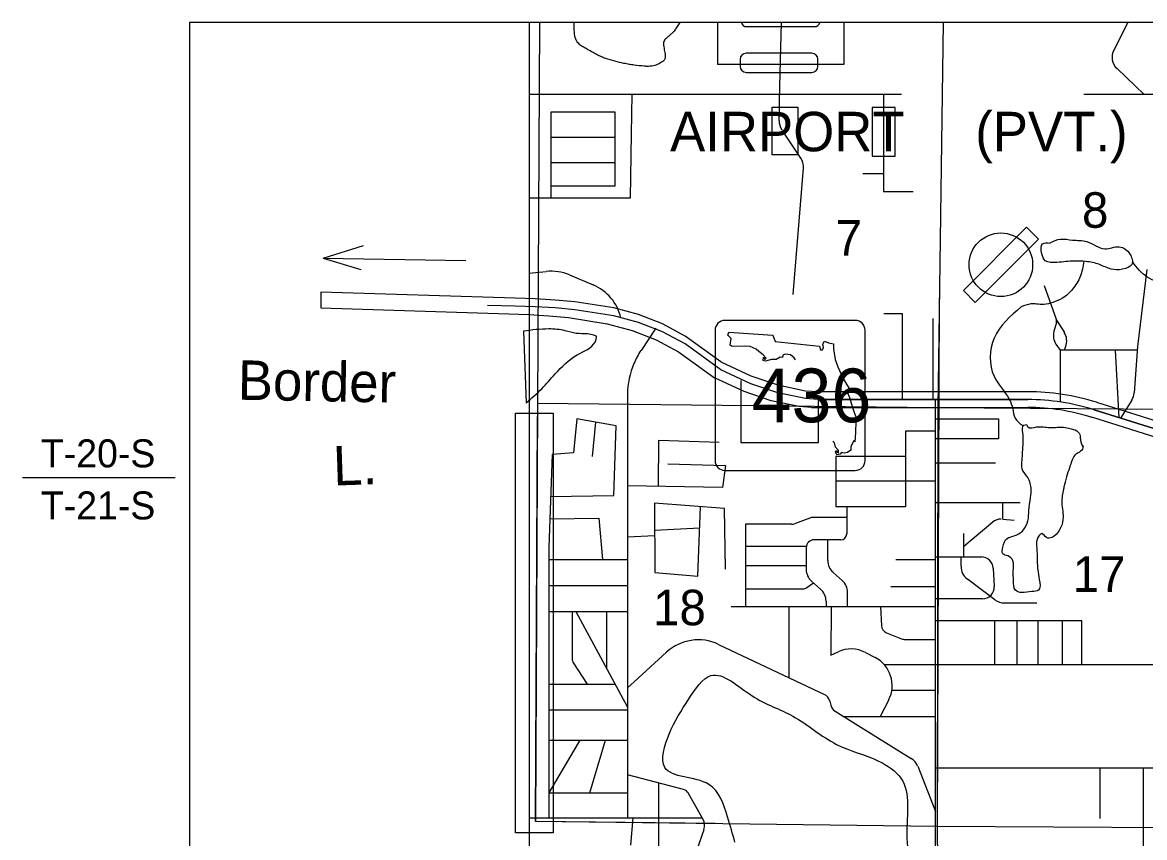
# Model space of a CAD drawing. Extents: x 2157516 to 2331756, y 2153820 to 2265756.
# Drawn here: x 2219640 to 2249249, y 2201230 to 2222724 of the extents above; entities that cross this region are included whole.
import ezdxf

# ---------------------------------------------------------------- set-up
doc = ezdxf.new("R2010")
doc.units = 0
for name, color, linetype in [('Default', 7, 'Continuous'), ('MapOutline_dp', 7, 'Continuous'), ('TextNotes', 7, 'Continuous')]:
    doc.layers.add(name, color=color, linetype=linetype)

msp = doc.modelspace()

# ---------------------------------------------------------------- linework, layer by layer
at = {"layer": 'Default'}
for p, q in [((2233280, 2222724), (2233232, 2212675)), ((2238754, 2222613), (2240534, 2222613)), ((2239629, 2221047), (2239669, 2222724)), ((2243932, 2222724), (2243791, 2212557)), ((2248805, 2222724), (2248437, 2221997)), ((2240472, 2221910), (2238734, 2221910)), ((2238578, 2221754), (2238578, 2221563)), ((2240628, 2221563), (2240628, 2221754)), ((2238734, 2221407), (2240472, 2221407)), ((2248522, 2221506), (2249008, 2221047)), ((2239608, 2220137), (2239629, 2221047)), ((2249008, 2221047), (2249234, 2220833)), ((2233004, 2220833), (2242838, 2220833)), ((2235711, 2219781), (2235728, 2220833)), ((2242359, 2220833), (2242359, 2218262)), ((2247650, 2220833), (2255920, 2220833)), ((2233594, 2218096), (2233594, 2220363)), ((2233594, 2220363), (2235271, 2220363)), ((2235271, 2220363), (2235271, 2218408)), ((2233594, 2219702), (2235271, 2219702)), ((2235682, 2218096), (2235711, 2219781)), ((2240178, 2219146), (2239754, 2219781)), ((2233594, 2219032), (2235271, 2219032)), ((2239977, 2215552), (2240246, 2218881)), ((2241814, 2218741), (2242359, 2218741)), ((2235271, 2218408), (2233599, 2218408)), ((2233022, 2218096), (2235682, 2218096)), ((2242359, 2218262), (2243142, 2218262)), ((2227571, 2216507), (2228636, 2216842)), ((2246760, 2216903), (2246761, 2216913)), ((2227571, 2216507), (2231343, 2216442)), ((2227571, 2216507), (2228565, 2216206)), ((2233005, 2216109), (2233457, 2216157)), ((2234076, 2216065), (2234701, 2215801)), ((2249311, 2216208), (2249064, 2214181)), ((2246601, 2215783), (2246919, 2214903)), ((2227515, 2215615), (2227515, 2215199)), ((2227515, 2215615), (2227515, 2215201)), ((2242367, 2215047), (2242854, 2215047)), ((2242854, 2215047), (2242854, 2212780)), ((2241613, 2214867), (2238177, 2214867)), ((2243669, 2212780), (2243669, 2214915)), ((2246923, 2214808), (2246859, 2214578)), ((2246926, 2214875), (2247132, 2214545)), ((2232862, 2214583), (2232929, 2212694)), ((2236354, 2214659), (2235962, 2214075)), ((2237917, 2214607), (2237917, 2211172)), ((2241873, 2211172), (2241873, 2214607)), ((2246911, 2214239), (2247021, 2214082)), ((2247167, 2214176), (2247131, 2214082)), ((2249064, 2214181), (2248974, 2212955)), ((2249057, 2214082), (2247021, 2214082)), ((2247021, 2214082), (2247021, 2212717)), ((2248473, 2214082), (2248566, 2212306)), ((2238598, 2213285), (2238598, 2211649)), ((2240632, 2212988), (2246167, 2212988)), ((2235608, 2212913), (2235608, 2201749)), ((2240632, 2212780), (2246167, 2212780)), ((2246167, 2212780), (2240632, 2212780)), ((2240647, 2211649), (2240647, 2212780)), ((2243735, 2196078), (2243735, 2212780)), ((2247984, 2212708), (2256111, 2210143)), ((2248910, 2212762), (2248611, 2212292)), ((2233232, 2212675), (2233179, 2201654)), ((2243791, 2212557), (2233232, 2212675)), ((2240462, 2212571), (2242532, 2212571)), ((2242532, 2212571), (2246167, 2212571)), ((2243791, 2212557), (2243775, 2201524)), ((2254920, 2212483), (2243791, 2212557)), ((2247922, 2212509), (2256048, 2209944)), ((2256048, 2209944), (2247922, 2212509)), ((2234272, 2212273), (2234183, 2211375)), ((2235303, 2212083), (2234272, 2212273)), ((2234763, 2212183), (2234675, 2211282)), ((2243735, 2212273), (2245391, 2212273)), ((2245391, 2212273), (2245391, 2211748)), ((2246131, 2212123), (2246131, 2212123)), ((2255985, 2209746), (2247859, 2212311)), ((2235242, 2210245), (2235303, 2212083)), ((2242953, 2209956), (2242953, 2211956)), ((2242953, 2211956), (2243735, 2211956)), ((2236419, 2210490), (2236435, 2211709)), ((2236435, 2211709), (2238022, 2211652)), ((2238598, 2211649), (2240647, 2211649)), ((2245391, 2211748), (2243735, 2211748)), ((2233615, 2211334), (2233528, 2208886)), ((2234183, 2211375), (2233615, 2211334)), ((2242933, 2211274), (2241102, 2211274)), ((2241102, 2211274), (2241102, 2209956)), ((2236668, 2211082), (2238188, 2211042)), ((2238188, 2211042), (2238112, 2210457)), ((2238177, 2210911), (2241613, 2210911)), ((2243735, 2211112), (2245312, 2211112)), ((2241102, 2210634), (2243735, 2210634)), ((2238112, 2210457), (2235608, 2210506)), ((2233575, 2210224), (2235242, 2210245)), ((2238169, 2209910), (2236319, 2210051)), ((2236319, 2210051), (2236325, 2208215)), ((2243735, 2210068), (2245969, 2210068)), ((2245511, 2209621), (2245511, 2210068)), ((2237460, 2208125), (2237535, 2209958)), ((2238188, 2208310), (2238169, 2209910)), ((2241102, 2209956), (2242953, 2209956)), ((2241389, 2209956), (2241389, 2209237)), ((2233554, 2209638), (2234848, 2209649)), ((2234848, 2209649), (2234947, 2208566)), ((2239937, 2209490), (2238719, 2209490)), ((2238723, 2209490), (2238723, 2207319)), ((2240414, 2209655), (2240011, 2209503)), ((2241389, 2209669), (2240487, 2209669)), ((2244476, 2208912), (2245244, 2209552)), ((2245511, 2209621), (2245811, 2209602)), ((2236322, 2209186), (2235608, 2209148)), ((2237512, 2209392), (2236322, 2209329)), ((2244476, 2208629), (2244476, 2209244)), ((2233528, 2208895), (2233528, 2201749)), ((2238723, 2208912), (2240324, 2208912)), ((2240320, 2208873), (2240320, 2208302)), ((2241233, 2209081), (2240529, 2209081)), ((2240890, 2208534), (2240890, 2209081)), ((2233528, 2208566), (2235608, 2208566)), ((2242687, 2208558), (2243735, 2208558)), ((2243735, 2208629), (2244943, 2208629)), ((2244407, 2208387), (2244413, 2208629)), ((2238723, 2208404), (2240320, 2208404)), ((2245254, 2208335), (2245283, 2207853)), ((2236325, 2208215), (2237460, 2208125)), ((2240341, 2207825), (2240514, 2207943)), ((2240463, 2207988), (2240702, 2207780)), ((2241271, 2208008), (2241030, 2208223)), ((2245299, 2207498), (2244573, 2208043)), ((2233528, 2207872), (2235608, 2207872)), ((2238723, 2207789), (2240224, 2207789)), ((2241410, 2207319), (2241410, 2207697)), ((2242554, 2207851), (2243735, 2207851)), ((2240844, 2207466), (2240844, 2207319)), ((2244971, 2207522), (2243735, 2207522)), ((2246410, 2207414), (2245549, 2207414)), ((2233528, 2207190), (2235608, 2207190)), ((2234143, 2207190), (2234143, 2205946)), ((2234243, 2207190), (2235608, 2204664)), ((2235063, 2205673), (2235063, 2207190)), ((2238340, 2207319), (2243735, 2207319)), ((2239867, 2205445), (2239867, 2207319)), ((2240982, 2207319), (2240969, 2206042)), ((2242284, 2207319), (2242307, 2206816)), ((2247591, 2206944), (2243735, 2206944)), ((2245299, 2205792), (2245299, 2206944)), ((2245886, 2205792), (2245886, 2206944)), ((2246443, 2205792), (2246443, 2206944)), ((2247088, 2205792), (2247088, 2206944)), ((2247591, 2205792), (2247591, 2206944)), ((2242437, 2206632), (2242836, 2206472)), ((2238009, 2206323), (2240800, 2205004)), ((2242933, 2206453), (2243735, 2206453)), ((2235777, 2205335), (2236633, 2206116)), ((2240969, 2206042), (2241160, 2206128)), ((2241885, 2206109), (2242138, 2205979)), ((2234178, 2205831), (2234543, 2205276)), ((2242378, 2205792), (2250599, 2205792)), ((2233528, 2205276), (2235277, 2205276)), ((2235608, 2205181), (2235777, 2205335)), ((2242580, 2205114), (2243735, 2205114)), ((2240941, 2204830), (2240968, 2204719)), ((2242497, 2204857), (2242271, 2204419)), ((2233528, 2204594), (2235608, 2204594)), ((2241084, 2204559), (2243094, 2203313)), ((2241309, 2204419), (2243735, 2204419)), ((2233528, 2203795), (2235608, 2203795)), ((2233540, 2202406), (2234360, 2203795)), ((2234613, 2202406), (2235029, 2203795)), ((2243262, 2203112), (2243735, 2201915)), ((2243735, 2203067), (2252299, 2203067)), ((2248074, 2201732), (2248074, 2203067)), ((2249218, 2196375), (2249218, 2203067)), ((2237086, 2202495), (2235608, 2202884)), ((2236435, 2200382), (2236435, 2202667)), ((2233528, 2202406), (2235608, 2202406)), ((2237602, 2201701), (2237215, 2202395)), ((2233007, 2201749), (2237576, 2201749)), ((2235743, 2201749), (2235687, 2201031)), ((2243775, 2201524), (2233179, 2201654)), ((2237159, 2200118), (2237624, 2201446)), ((2254804, 2201455), (2243775, 2201524)), ((2243775, 2201524), (2243876, 2190600))]:
    msp.add_line(p, q, dxfattribs=at)
for points in [[(2233007, 2222724), (2233007, 2190644)], [(2241310, 2222724), (2241310, 2221613), (2237985, 2221613), (2237985, 2222724)], [(2238071, 2213772), (2237125, 2214455), (2236530, 2214773), (2235896, 2215020), (2235242, 2215195), (2234215, 2215357), (2233697, 2215404), (2233172, 2215435), (2232643, 2215454), (2227515, 2215615)], [(2243831, 2215454), (2243775, 2201524), (2243829, 2195744)], [(2227515, 2215199), (2232474, 2215038), (2233002, 2215019), (2233528, 2214988), (2234045, 2214940), (2235073, 2214778), (2235727, 2214603), (2236360, 2214357), (2236955, 2214038), (2237902, 2213356)], [(2238071, 2213564), (2237125, 2214246), (2236530, 2214565), (2235896, 2214812), (2235242, 2214987), (2234215, 2215149), (2233697, 2215196), (2233172, 2215227), (2232643, 2215246), (2231914, 2215259)], [(2240040, 2213828), (2239999, 2213881), (2239910, 2213956), (2239766, 2213977), (2239704, 2213949), (2239697, 2213888), (2239635, 2213894), (2239525, 2213833), (2239402, 2213833), (2239244, 2213791), (2239189, 2213805), (2239196, 2213894), (2239230, 2213833), (2239265, 2213867), (2239189, 2213956), (2239072, 2214046), (2238997, 2214107), (2238846, 2214176), (2238688, 2214183), (2238366, 2214176), (2238318, 2214210), (2238345, 2214389), (2238249, 2214478), (2238283, 2214560)], [(2238283, 2214560), (2239436, 2214478), (2239498, 2214313), (2240672, 2214183), (2240699, 2214087), (2240747, 2214087), (2240781, 2214155), (2240761, 2214238), (2240802, 2214320), (2240905, 2214272), (2241042, 2214252), (2241042, 2214121), (2241083, 2213840), (2241152, 2213640), (2241296, 2213331), (2241392, 2213167), (2241447, 2213091), (2241406, 2212974), (2241461, 2212830), (2241529, 2212631), (2241577, 2212466), (2241632, 2212322), (2241632, 2212192), (2241619, 2211931), (2241612, 2211780), (2241605, 2211663), (2241577, 2211697), (2241543, 2211622), (2241495, 2211539), (2241495, 2211443), (2241413, 2211381), (2241323, 2211368), (2241248, 2211381), (2241221, 2211340), (2241131, 2211326), (2241090, 2211402), (2241111, 2211436), (2241138, 2211388), (2241172, 2211374), (2241172, 2211436), (2241097, 2211525), (2241070, 2211635), (2241023, 2211686)], [(2238071, 2213772), (2238856, 2213407), (2239568, 2213166), (2240306, 2213011), (2240632, 2212988)], [(2240462, 2212571), (2240136, 2212595), (2239398, 2212750), (2238686, 2212990), (2237902, 2213356)], [(2240632, 2212780), (2240306, 2212803), (2239568, 2212958), (2238856, 2213198), (2238071, 2213564)], [(2237923, 2201596), (2233179, 2201654), (2233231, 2212330)]]:
    msp.add_lwpolyline(points, dxfattribs=at)
for points in [[(2239427, 2220493), (2240098, 2220493), (2240098, 2219231), (2239427, 2219231)], [(2242670, 2220477), (2242064, 2220477), (2242064, 2219198), (2242670, 2219198)], [(2246134, 2217324), (2244468, 2215658), (2244783, 2215342), (2246446, 2217012)], [(2232654, 2212419), (2233645, 2212419), (2233645, 2201352), (2232654, 2201352)]]:
    msp.add_lwpolyline(points, close=True, dxfattribs=at)
msp.add_circle((2245457, 2216335), 839, dxfattribs=at)
for centre, radius, start, end in [((2238754, 2222769), 156, 197.0342, 269.9999), ((2240534, 2222769), 156, 270, 342.966), ((2238734, 2221754), 156, 90, 179.9999), ((2240472, 2221754), 156, 359.9999, 89.9999), ((2248808, 2221809), 416, 153.1187, 226.5909), ((2238734, 2221563), 156, 179.9999, 269.9999), ((2240472, 2221563), 156, 270, 359.9999), ((2240024, 2220127), 416, 178.644, 213.6898), ((2239831, 2218915), 416, 355.3748, 33.6898), ((2233590, 2214915), 1249, 67.0716, 96.1), ((2234214, 2214651), 1249, 13.2089, 67.0715), ((2238177, 2214607), 260, 90, 180), ((2241613, 2214607), 260, 0, 90), ((2246772, 2214850), 156, 344.4273, 19.855), ((2247260, 2214466), 416, 164.4273, 213.1468), ((2246779, 2214325), 416, 338.9623, 31.9533), ((2237689, 2212913), 2082, 146.0936, 156.841), ((2237689, 2212913), 2082, 156.841, 179.9999), ((2246167, 2206950), 6037, 72.4812, 90), ((2246167, 2206950), 5829, 72.4812, 90), ((2246167, 2206950), 5829, 72.4812, 90), ((2248559, 2212985), 416, 327.5787, 355.7945), ((2246167, 2206950), 5621, 72.4812, 90), ((2238177, 2211172), 260, 180, 270), ((2241613, 2211172), 260, 270, 360), ((2239937, 2209698), 208, 270, 290.6759), ((2240487, 2209461), 208, 90, 110.6758), ((2245444, 2209312), 312, 86.4237, 129.8056), ((2241233, 2209237), 156, 270, 360), ((2240529, 2208873), 208, 90, 180), ((2241307, 2208534), 416, 179.9998, 228.3017), ((2244943, 2208317), 312, 3.391, 89.9999), ((2240737, 2208302), 416, 179.9998, 228.9448), ((2244823, 2208376), 416, 178.531, 233.0757), ((2240994, 2207697), 416, 359.9998, 48.3019), ((2240224, 2207997), 208, 270, 304.4139), ((2240428, 2207466), 416, 359.9998, 48.9448), ((2244971, 2207835), 312, 270, 3.3911), ((2245549, 2207831), 416, 233.0757, 269.9999), ((2242515, 2206825), 208, 182.6194, 248.1262), ((2242933, 2206714), 260, 248.1264, 270), ((2237475, 2205194), 1249, 64.6932, 132.3923), ((2241503, 2205369), 833, 62.7275, 114.3254), ((2234352, 2205946), 208, 179.9999, 213.3261), ((2241756, 2205238), 833, 332.7527, 62.7274), ((2240688, 2204768), 260, 13.6269, 64.693), ((2241221, 2204780), 260, 193.6265, 238.2156), ((2242875, 2202959), 416, 21.5619, 58.2156), ((2237033, 2202294), 208, 29.1759, 75.2489), ((2237329, 2201549), 312, 340.6991, 29.1759)]:
    msp.add_arc(centre, radius, start, end, dxfattribs=at)
for points in [[(2236983, 2222724), (2236953, 2222671), (2236920, 2222619), (2236885, 2222568), (2236851, 2222518), (2236788, 2222443), (2236714, 2222380), (2236642, 2222319), (2236581, 2222252), (2236557, 2222192), (2236556, 2222122), (2236586, 2221966), (2236602, 2221814), (2236583, 2221748), (2236564, 2221720), (2236551, 2221707), (2236535, 2221694), (2236476, 2221656), (2236416, 2221625), (2236295, 2221584), (2236111, 2221566), (2236049, 2221570), (2235780, 2221598), (2235646, 2221618), (2235512, 2221644), (2235269, 2221702), (2235030, 2221773), (2234915, 2221818), (2234805, 2221870), (2234697, 2221928), (2234589, 2221990), (2234485, 2222048), (2234384, 2222110), (2234298, 2222186), (2234265, 2222232), (2234251, 2222258), (2234245, 2222271), (2234239, 2222285), (2234214, 2222377), (2234204, 2222470), (2234202, 2222562), (2234202, 2222655), (2234201, 2222724)], [(2246761, 2216913), (2247030, 2217010), (2247346, 2216985), (2247729, 2216944), (2248199, 2216756), (2248581, 2216806), (2248864, 2216615), (2248910, 2216345), (2248669, 2216216), (2248365, 2216220), (2248057, 2216340), (2247695, 2216420), (2247396, 2216432), (2246938, 2216395), (2246630, 2216440), (2246539, 2216623), (2246560, 2216890), (2246760, 2216903)], [(2247643, 2216425), (2247608, 2216216), (2247550, 2216024), (2247350, 2215692), (2247088, 2215455), (2246826, 2215342), (2246593, 2215288), (2246397, 2215296), (2246248, 2215301), (2245991, 2215221)], [(2250768, 2215197), (2250399, 2215384), (2250016, 2215696), (2249555, 2215891), (2249105, 2216191), (2248939, 2216400)], [(2245991, 2215221), (2245282, 2214402), (2245278, 2213394), (2245678, 2212790), (2245771, 2212542), (2245833, 2212291), (2246038, 2212087)], [(2232929, 2212694), (2233345, 2213066), (2233699, 2213455), (2234278, 2213957), (2234749, 2214292), (2234781, 2214368), (2234786, 2214439), (2234720, 2214474), (2234553, 2214509), (2234251, 2214524), (2233963, 2214595), (2233529, 2214641), (2232862, 2214583)], [(2247136, 2210536), (2247109, 2210417), (2247067, 2210060), (2247096, 2209614), (2246996, 2209327), (2246809, 2209144), (2246664, 2209140), (2246535, 2209244), (2246414, 2209086), (2246406, 2208870), (2246414, 2208525), (2246431, 2208283), (2246472, 2208034), (2246447, 2207751), (2246277, 2207718), (2246006, 2207689), (2245844, 2207751), (2245790, 2208009), (2245786, 2208267), (2245774, 2208529), (2245645, 2208654), (2245511, 2208712), (2245507, 2208891), (2245624, 2209119), (2245786, 2209178), (2246052, 2209340), (2246173, 2209585), (2246198, 2209852), (2246239, 2210189), (2246256, 2210455), (2246144, 2210758), (2246019, 2210954), (2246019, 2211183), (2246031, 2211391), (2246048, 2211653), (2246036, 2211906), (2246065, 2212106), (2246131, 2212123)], [(2246131, 2212123), (2246171, 2212056), (2246399, 2212056), (2246748, 2212043), (2247164, 2212043), (2247312, 2212003)], [(2247312, 2212003), (2247500, 2211922), (2247553, 2211788), (2247567, 2211667), (2247629, 2211557), (2247629, 2211561), (2247629, 2211557), (2247437, 2211337), (2247288, 2211037), (2247209, 2210804), (2247136, 2210536)], [(2238441, 2201107), (2238245, 2201773), (2237750, 2202631), (2236588, 2203077), (2236704, 2203960), (2237225, 2204885), (2237808, 2205501), (2238891, 2204968), (2239969, 2204431), (2241123, 2203685), (2242227, 2203248), (2242822, 2202794), (2242974, 2201315), (2243208, 2199644), (2243241, 2198575), (2243141, 2197706), (2242740, 2196670), (2242305, 2196302), (2241998, 2195962)]]:
    msp.add_spline(points, degree=3, dxfattribs=at)
at = {"layer": 'MapOutline_dp'}
msp.add_lwpolyline([(2224044, 2180484), (2265958, 2180484), (2265958, 2222724), (2224044, 2222724)], close=True, dxfattribs=at)
at = {"layer": 'TextNotes'}
msp.add_line((2219640, 2210727), (2223666, 2210727), dxfattribs=at)

# ---------------------------------------------------------------- texts
at = {"layer": 'Default'}
for s, height, rotation, p in [('AIRPORT', 1040.9, 360, (2236729, 2219326)), ('(PVT.)', 1040.9, 360, (2244781, 2219326)), ('8', 937, 360, (2247597, 2217309)), ('7', 937, 360, (2241095, 2216573)), ('Border', 1040.9, 358.9113, (2225315, 2212776)), ('L.', 1040.9, 1.9219, (2227851, 2210511)), ('17', 936.8, 360, (2247353, 2207709)), ('18', 936.8, 360, (2236280, 2206827))]:
    msp.add_text(s, height=height, rotation=rotation, dxfattribs=at).set_placement(p)
msp.add_text('436', height=1415.7, dxfattribs=at).set_placement((2238881, 2212181))
at = {"layer": 'TextNotes'}
for s, p in [('T-20-S', (2220126, 2210991)), ('T-21-S', (2220126, 2209618))]:
    msp.add_text(s, height=739.2, dxfattribs=at).set_placement(p)

doc.saveas('drawing.dxf')
